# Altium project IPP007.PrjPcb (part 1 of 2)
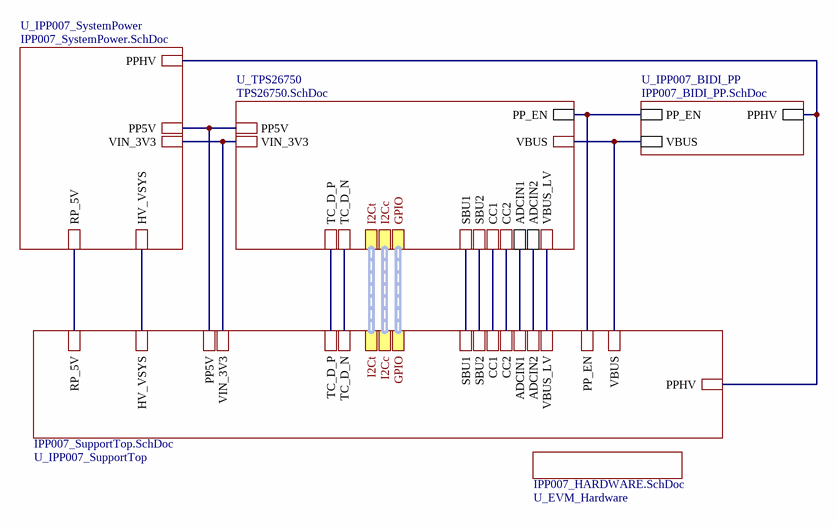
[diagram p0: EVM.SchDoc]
CopyrightYear: 2025; PCB_Layout: Chuck Branch; PCB_Rev: A3; PRJ_Customer: Public Release; PRJ_Engineer: Conner Gillette; PRJ_Number: IPP007; PRJ_Title: TPS26750 EVM; SCH_Rev: A3; TechSupport: http://www.ti.com/support; TID: 11450
12 sheets, 258 parts. Net scope: hierarchical (ports join the sheet entries above them; power ports are global).
Board file: IPP007_EVM.PcbDoc
Sheets:
  EVM.SchDoc
    U_EVM_Hardware = IPP007_HARDWARE.SchDoc
    U_TPS26750 = TPS26750.SchDoc
      U_MD = MOISTURE_DETECT.SchDoc
    U_IPP007_SystemPower = IPP007_SystemPower.SchDoc
      U_PP5V_SUPPLY = PP5V_SUPPLY.SchDoc
      U_IPP007_TC_POWER = IPP007_TC_POWER.SchDoc
    U_IPP007_SupportTop = IPP007_SupportTop.SchDoc
      U_IPP007_CONNECTORS = IPP007_CONNECTORS.SchDoc
      U_IPP007_RP_HOST = IPP007_RP_HOST.SchDoc
      U_IPP007_HUB = IPP007_HUB.SchDoc
    U_IPP007_BIDI_PP = IPP007_BIDI_PP.SchDoc

## Sheet EVM.SchDoc
size 431 x 279 mm; Date: Not shown in title block; ApprovedBy: Not shown in title block; CheckedBy: Not shown in title block; Author: Not shown in title block; CompanyName: Not shown in title block; Engineer: Not shown in title block; Organization: Not shown in title block; Address1: Not shown in title block; Address2: Not shown in title block; Address3: Not shown in title block; Address4: Not shown in title block; DocumentNumber: 1; Revision: Use project parameter SCH_Rev; SheetNumber: 1; SheetTotal: 14; PageSetup: Record=PageOptions¦CenterHorizontal=True¦CenterVertical=True¦PrintScale=0.97¦XCorrection=1.00¦YCorrection=1.00¦PrintKind=0¦BorderSize=5000000¦LeftOffset=0¦BottomOffset=0¦Orientation=2¦PaperLength=1000¦PaperWidth=1000¦Scale=100¦PaperSource=15¦PrintQuality=600¦MediaType=1¦DitherType=10¦PaperKind=Letter¦PrintScaleMode=1

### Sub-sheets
U_EVM_Hardware = IPP007_HARDWARE.SchDoc: no entries
U_IPP007_BIDI_PP = IPP007_BIDI_PP.SchDoc: PP_EN, VBUS, PPHV
U_IPP007_SupportTop = IPP007_SupportTop.SchDoc: CC1, CC2, PP_EN, ADCIN1, ADCIN2, HV_VSYS, PPHV, VBUS, VBUS_LV, PP5V, VIN_3V3, RP_5V, SBU1, SBU2, TC_D_P, TC_D_N, I2Ct (harness I2C), I2Cc (harness I2C), GPIO (harness GPIO)
U_IPP007_SystemPower = IPP007_SystemPower.SchDoc: HV_VSYS, PP5V, VIN_3V3, RP_5V, PPHV
U_TPS26750 = TPS26750.SchDoc: CC1, CC2, ADCIN2, ADCIN1, PP_EN, VBUS, VBUS_LV, PP5V, VIN_3V3, SBU1, SBU2, TC_D_P, TC_D_N, I2Ct (harness I2C), I2Cc (harness I2C), GPIO (harness GPIO)

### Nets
ADCIN1: sheet U_TPS26750/ADCIN1, sheet U_IPP007_SupportTop/ADCIN1
ADCIN2: sheet U_TPS26750/ADCIN2, sheet U_IPP007_SupportTop/ADCIN2
CC1: sheet U_TPS26750/CC1, sheet U_IPP007_SupportTop/CC1
CC2: sheet U_TPS26750/CC2, sheet U_IPP007_SupportTop/CC2
D3_N: sheet U_TPS26750/TC_D_N, sheet U_IPP007_SupportTop/TC_D_N
D3_P: sheet U_TPS26750/TC_D_P, sheet U_IPP007_SupportTop/TC_D_P
HV_VSYS: sheet U_IPP007_SystemPower/HV_VSYS, sheet U_IPP007_SupportTop/HV_VSYS
PP5V: sheet U_TPS26750/PP5V, sheet U_IPP007_SystemPower/PP5V, sheet U_IPP007_SupportTop/PP5V
PP_EN: sheet U_TPS26750/PP_EN, sheet U_IPP007_SupportTop/PP_EN, sheet U_IPP007_BIDI_PP/PP_EN
PPHV: sheet U_IPP007_SystemPower/PPHV, sheet U_IPP007_SupportTop/PPHV, sheet U_IPP007_BIDI_PP/PPHV
RP_5V: sheet U_IPP007_SystemPower/RP_5V, sheet U_IPP007_SupportTop/RP_5V
SBU1: sheet U_TPS26750/SBU1, sheet U_IPP007_SupportTop/SBU1
SBU2: sheet U_TPS26750/SBU2, sheet U_IPP007_SupportTop/SBU2
VBUS: sheet U_TPS26750/VBUS, sheet U_IPP007_SupportTop/VBUS, sheet U_IPP007_BIDI_PP/VBUS
VBUS_LV: sheet U_TPS26750/VBUS_LV, sheet U_IPP007_SupportTop/VBUS_LV
VIN_3V3: sheet U_TPS26750/VIN_3V3, sheet U_IPP007_SystemPower/VIN_3V3, sheet U_IPP007_SupportTop/VIN_3V3

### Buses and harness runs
harness sheet U_IPP007_SupportTop/GPIO = sheet U_TPS26750/GPIO
harness sheet U_IPP007_SupportTop/I2Cc = sheet U_TPS26750/I2Cc
harness sheet U_IPP007_SupportTop/I2Ct = sheet U_TPS26750/I2Ct

## Sheet IPP007_HARDWARE.SchDoc
size 431 x 279 mm; Date: Not shown in title block; ApprovedBy: Not shown in title block; CheckedBy: Not shown in title block; Author: Not shown in title block; CompanyName: Not shown in title block; Engineer: Not shown in title block; Organization: Not shown in title block; Address1: Not shown in title block; Address2: Not shown in title block; Address3: Not shown in title block; Address4: Not shown in title block; DocumentNumber: 14; Revision: Use project parameter SCH_Rev; SheetNumber: 14; SheetTotal: 14; PageSetup: Record=PageOptions¦CenterHorizontal=True¦CenterVertical=True¦PrintScale=0.97¦XCorrection=1.00¦YCorrection=1.00¦PrintKind=0¦BorderSize=5000000¦LeftOffset=0¦BottomOffset=0¦Orientation=2¦PaperLength=1000¦PaperWidth=1000¦Scale=100¦PaperSource=15¦PrintQuality=600¦MediaType=1¦DitherType=10¦PaperKind=Letter¦PrintScaleMode=1
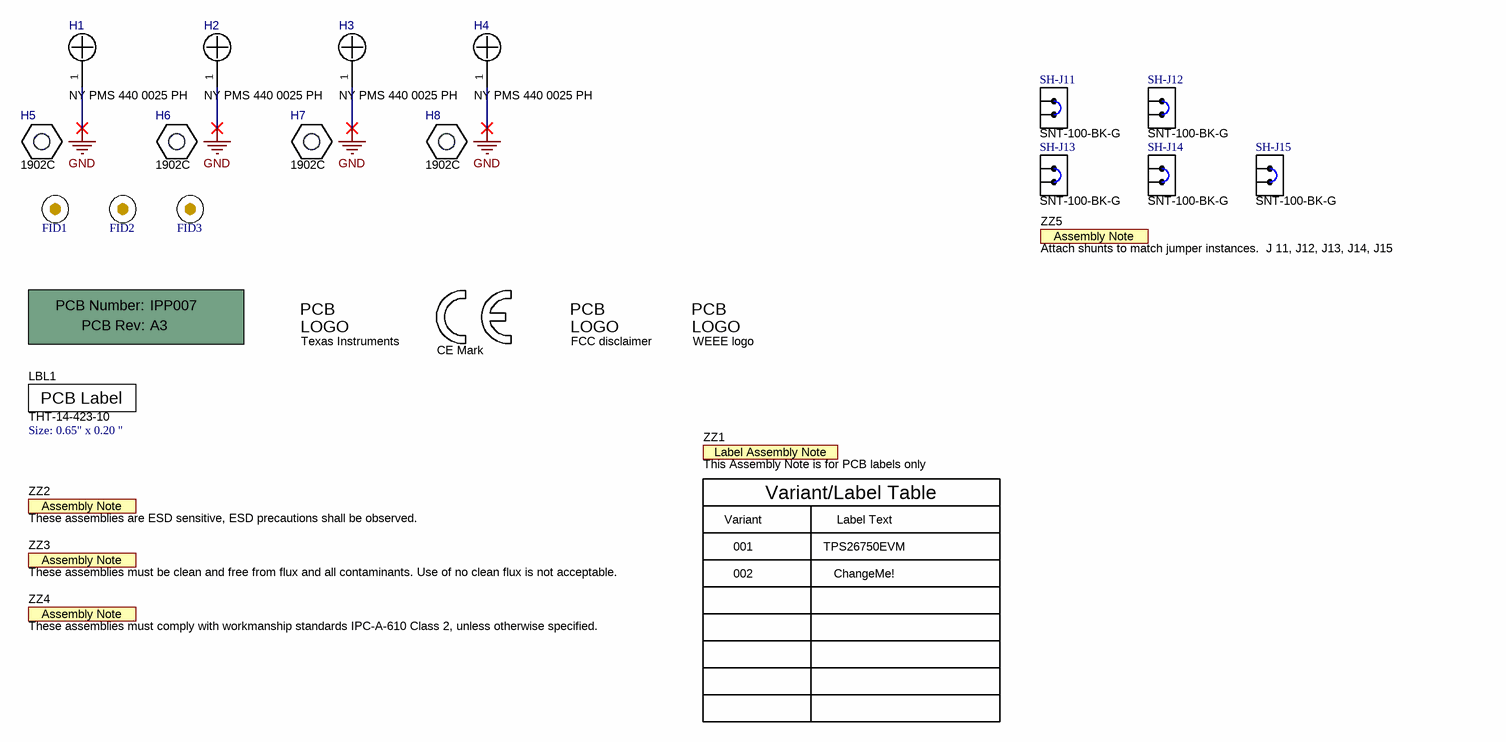
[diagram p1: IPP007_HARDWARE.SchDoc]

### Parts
!PCB1  Printed Circuit Board  (value not drawn)  (mechanical)
FID1  Fiducial  [Fiducial10-20]  (value not drawn)
FID2  Fiducial  [Fiducial10-20]  (value not drawn)
FID3  Fiducial  [Fiducial10-20]  (value not drawn)
H1  NY PMS 440 0025 PH  [NY PMS 440 0025 PH]
H2  NY PMS 440 0025 PH  [NY PMS 440 0025 PH]
H3  NY PMS 440 0025 PH  [NY PMS 440 0025 PH]
H4  NY PMS 440 0025 PH  [NY PMS 440 0025 PH]
H5  1902C  [Keystone_1902C]
H6  1902C  [Keystone_1902C]
H7  1902C  [Keystone_1902C]
H8  1902C  [Keystone_1902C]
LBL1  THT-14-423-10  Note: Size: 0.65" x 0.20 "  [Label_650x200]
Logo1  CE Mark  [CE_Mark_5mm]  (no BOM)
Logo2  Texas Instruments  [TI_Symbol_Overlay_Small]  (no BOM)
Logo3  FCC disclaimer  [FCC_disclaimer_stacked]  (no BOM)
Logo4  WEEE logo  [WEEE_Minimum]  (no BOM)
SH-J11  SNT-100-BK-G  [SNT-100-BK-G]
SH-J12  SNT-100-BK-G  [SNT-100-BK-G]
SH-J13  SNT-100-BK-G  [SNT-100-BK-G]
SH-J14  SNT-100-BK-G  [SNT-100-BK-G]
SH-J15  SNT-100-BK-G  [SNT-100-BK-G]
ZZ1  This Assembly Note is for PCB labels only  [AssemblyNoteLabel]  (no BOM)
ZZ2  These assemblies are ESD sensitive, ESD precautions shall be observed.  [AssemblyNote]  (no BOM)
ZZ3  These assemblies must be clean and free from flux and all contaminants. Use of no clean flux is not acceptable.  [AssemblyNote]  (no BOM)
ZZ4  These assemblies must comply with workmanship standards IPC-A-610 Class 2, unless otherwise specified.  [AssemblyNote]  (no BOM)
ZZ5  Attach shunts to match jumper instances.  J 11, J12, J13, J14, J15  [AssemblyNote]  (no BOM)

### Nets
GND: H1.1 H2.1 H3.1 H4.1

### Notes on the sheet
- Variant
- 001
- (near ZZ1) Variant/Label Table
- Label Text
- TPS26750EVM
- 002
- ChangeMe!

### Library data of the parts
!PCB1 = CMP-0003618-2: Manufacturer: Any; PartNumber: IPP007
FID1-FID3 = CMP-0077181-1: Fiducial mark.  There is nothing to buy or mount.
H1-H4 = CMP-0003617-1: Machine Screw, Round, #4-40 x 1/4, Nylon, Philips panhead; Manufacturer: B&F Fastener Supply; CompType: Hardware
H5-H8 = CMP-0003610-1: Standoff, Hex, 0.5"L #4-40 Nylon; Manufacturer: Keystone; CompType: Hardware
LBL1 = CMP-0003625-1: Thermal Transfer Printable Labels, 0.650" W x 0.200" H - 10,000 per roll; Manufacturer: Brady
Logo1 = CMP-0074844-1: SymbolCreator: a0412235
Logo2 = CMP-0074838-1: Texas Instrument Corporate Signature; SymbolCreator: a0412235; Lib Reference: TI_Logo
Logo3 = CMP-0074847-1: FCC_disclaimer
Logo4 = CMP-0074769-3: Manufacturer: Texas Instruments; CompType: IC; AEC Category: Q200
SH-J11-SH-J15 = CMP-0003623-3: Shunt, 100mil, Gold plated, Black; Manufacturer: Samtec; Alternate Manufacturer: 3M; Alternate PartNumber: 969102-0000-DA; Value: 1x2; Note: You can "mate" this to a header by matching the designator.  i.e. use SH-J3 for header J3
ZZ1 = CMP-0003616-3
ZZ2 = CMP-0077236-1
ZZ3 = CMP-0077237-1
ZZ4 = CMP-0077238-1
ZZ5 = CMP-0077238-1: These assemblies must comply with workmanship standards IPC-A-610 Class 2, unless otherwise specified.

## Sheet TPS26750.SchDoc
size 558 x 431 mm; Date: Not shown in title block; ApprovedBy: Not shown in title block; CheckedBy: Not shown in title block; Author: Not shown in title block; CompanyName: Not shown in title block; Engineer: Not shown in title block; Organization: Not shown in title block; Address1: Not shown in title block; Address2: Not shown in title block; Address3: Not shown in title block; Address4: Not shown in title block; DocumentNumber: 2; Revision: Use project parameter SCH_Rev; SheetNumber: 2; SheetTotal: 14; PageSetup: Record=PageOptions¦CenterHorizontal=True¦CenterVertical=True¦PrintScale=1.00¦XCorrection=1.00¦YCorrection=1.00¦PrintKind=0¦BorderSize=5000000¦LeftOffset=0¦BottomOffset=0¦Orientation=2¦PaperLength=1000¦PaperWidth=1000¦Scale=100¦PaperSource=15¦PrintQuality=600¦MediaType=1¦DitherType=10¦PaperKind=Letter¦PrintScaleMode=1
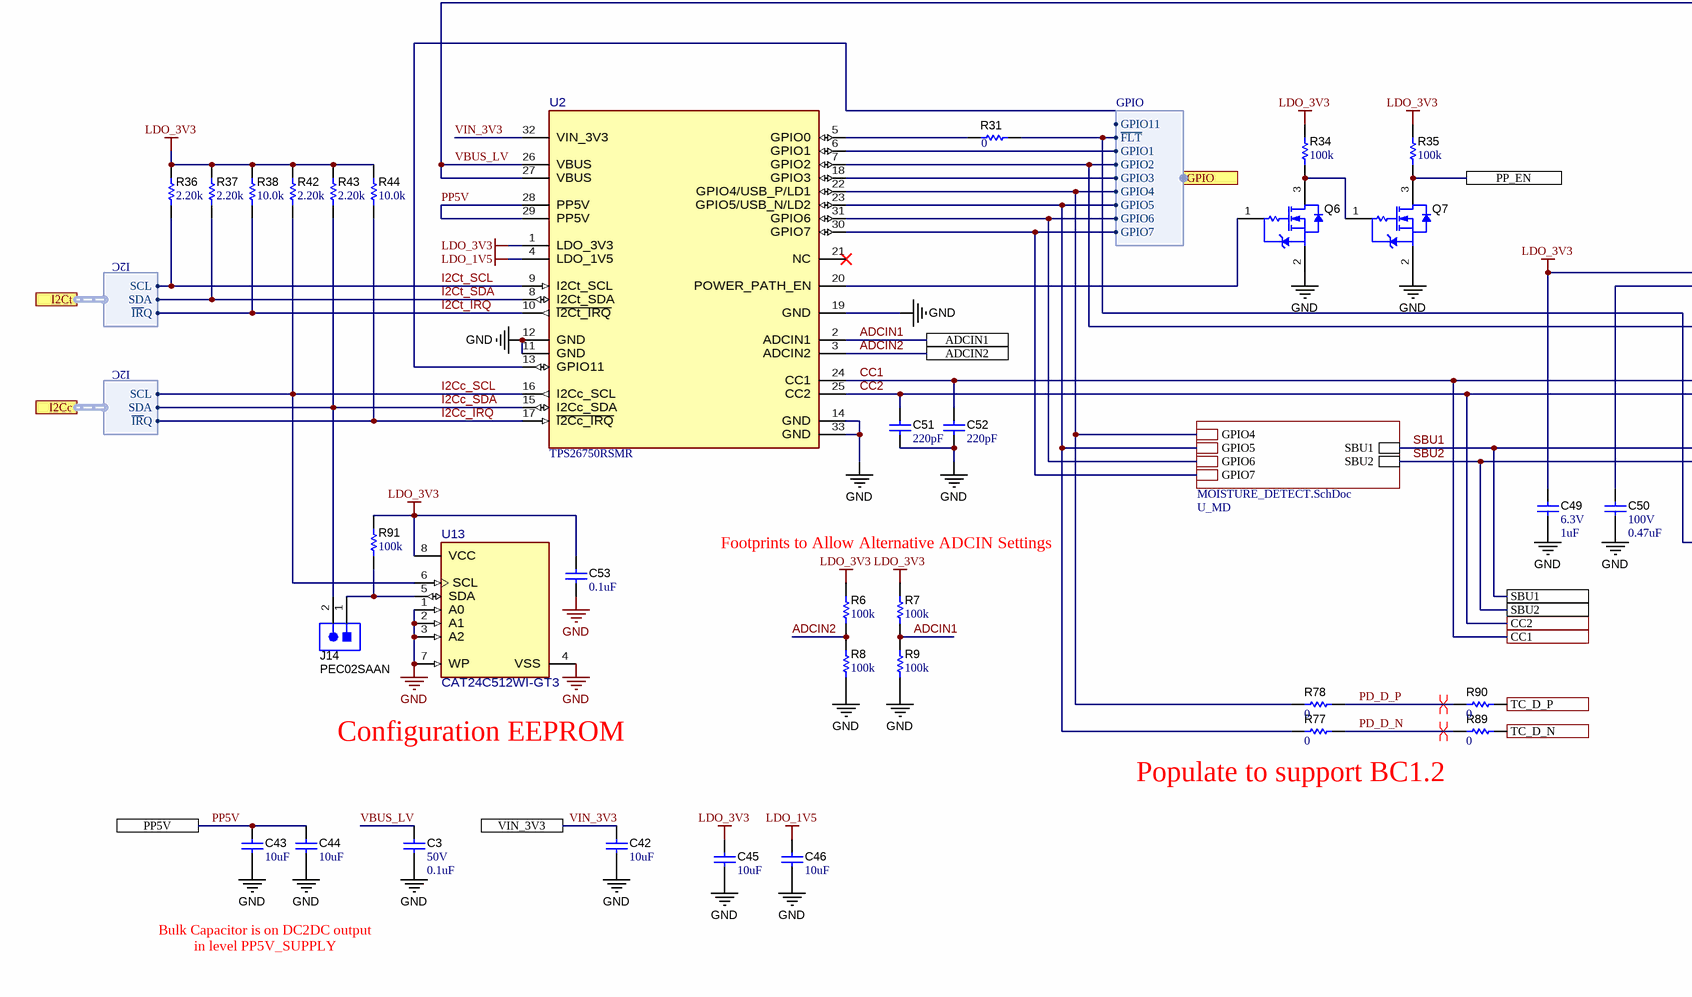
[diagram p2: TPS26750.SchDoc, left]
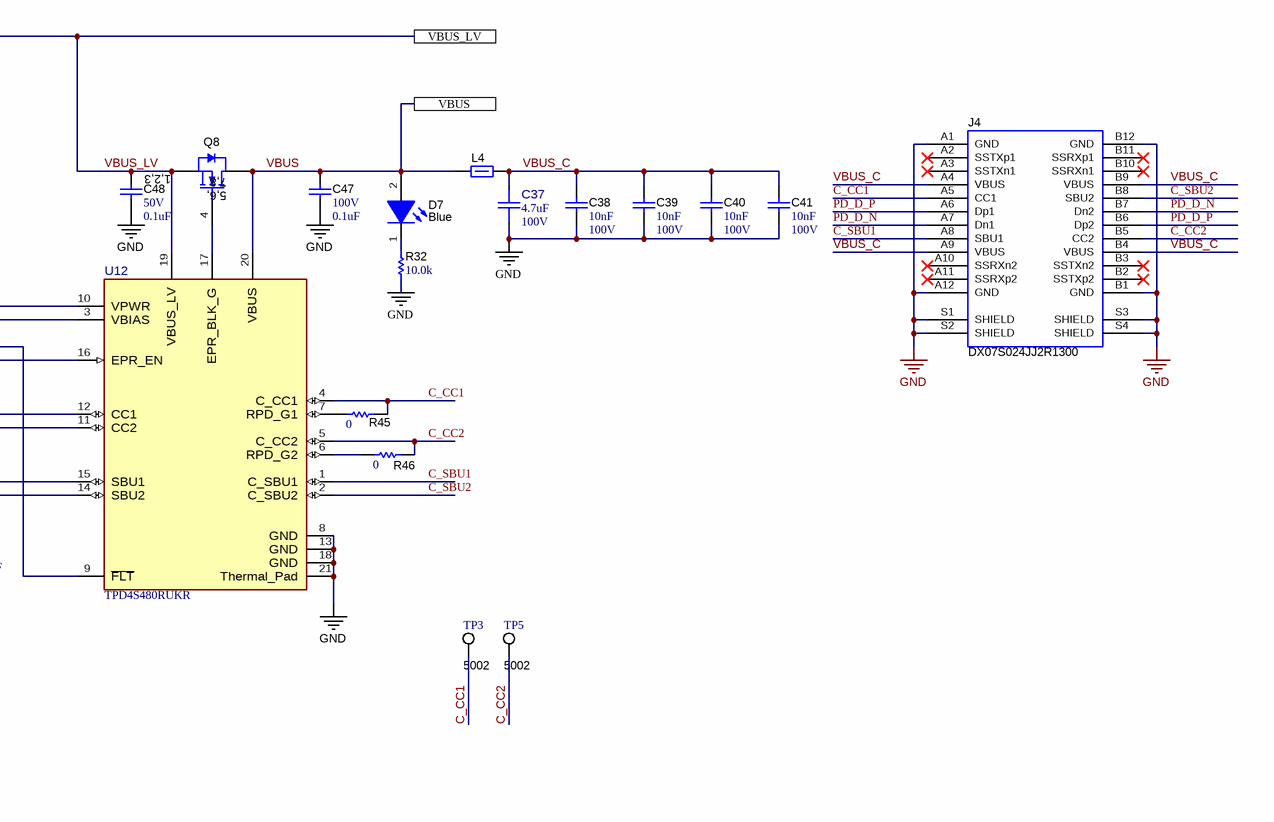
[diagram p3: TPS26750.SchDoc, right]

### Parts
C3  VDC_V: 50V  ValueDisplayed: 0.1uF  [0402L]  (hidden comment: C1005X5R1H104K050BB)
C37  ValueDisplayed: 4.7uF  VDC_V: 100V  [FP-C2012X5R2A475K125AC_0805-MFG]  (hidden comment: C2012X5R2A475K125AC)
C38  Cap_F: 10nF  VDC_V: 100V  [0603L]  (hidden comment: C0603X103K1RACTU)
C39  Cap_F: 10nF  VDC_V: 100V  [0603L]  (hidden comment: C0603X103K1RACTU)
C40  Cap_F: 10nF  VDC_V: 100V  [0603L]  (hidden comment: C0603X103K1RACTU)
C41  Cap_F: 10nF  VDC_V: 100V  [0603L]  (hidden comment: C0603X103K1RACTU)
C42  ValueDisplayed: 10uF  [0402_070]  (hidden comment: CL05A106MP5NUNC)
C43  ValueDisplayed: 10uF  [0603L]  (hidden comment: GRM188R61E106MA73D)
C44  ValueDisplayed: 10uF  [0603L]  (hidden comment: GRM188R61E106MA73D)
C45  ValueDisplayed: 10uF  [0402_070]  (hidden comment: CL05A106MP5NUNC)
C46  ValueDisplayed: 10uF  [0402_070]  (hidden comment: CL05A106MP5NUNC)
C47  VDC_V: 100V  ValueDisplayed: 0.1uF  [0402L]  (hidden comment: GRM155R62A104KE14D)
C48  VDC_V: 50V  ValueDisplayed: 0.1uF  [0402L]  (hidden comment: C1005X5R1H104K050BB)
C49  VDC_V: 6.3V  ValueDisplayed: 1uF  [0201_033]  (hidden comment: GRM033R60J105MEA2D)
C50  VDC_V: 100V  ValueDisplayed: 0.47uF  [1206_180]  (hidden comment: C3216X7R2A474K160AA)
C51  ValueDisplayed: 220pF  [0201_033L]  (hidden comment: CGA1A2X7R1H221K030BA)
C52  ValueDisplayed: 220pF  [0201_033L]  (hidden comment: CGA1A2X7R1H221K030BA)
C53  ValueDisplayed: 0.1uF  [0402L]  (hidden comment: CGA2B3X7R1H104K050BB)
D7  value Blue  [WL-SMCW_Blue]  (hidden comment: 150060BS75000)
J4  DX07S024JJ2R1300  [JAE_DX07S024JJ2R1300]
J14  PEC02SAAN  [CONN_PEC02SAAN]
L4  742792021  [0805L]  (value not drawn)
Q6  CSD17484F4T  [YJJ0003A]  (value not drawn)
Q7  CSD17484F4T  [YJJ0003A]  (value not drawn)
Q8  CSD17581Q3A  [DNH0008A]  (value not drawn)
R6  ValueDisplayed: 100k  [0603L]  (hidden comment: RC0603FR-07100KL)
R7  ValueDisplayed: 100k  [0603L]  (hidden comment: RC0603FR-07100KL)
R8  ValueDisplayed: 100k  [0603L]  (hidden comment: RC0603FR-07100KL)
R9  ValueDisplayed: 100k  [0603L]  (hidden comment: RC0603FR-07100KL)
R31  ValueDisplayed: 0  [0402]  (hidden comment: CRCW04020000Z0ED)
R32  ValueDisplayed: 10.0k  [0402L]  (hidden comment: CRCW040210K0FKED)
R34  ValueDisplayed: 100k  [0201L]  (hidden comment: RC0201FR-07100KL)
R35  ValueDisplayed: 100k  [0201L]  (hidden comment: RC0201FR-07100KL)
R36  ValueDisplayed: 2.20k  [0201L]  (hidden comment: CRCW02012K20FKED)
R37  ValueDisplayed: 2.20k  [0201L]  (hidden comment: CRCW02012K20FKED)
R38  ValueDisplayed: 10.0k  [0201L]  (hidden comment: CRCW020110K0FKED)
R42  ValueDisplayed: 2.20k  [0201L]  (hidden comment: CRCW02012K20FKED)
R43  ValueDisplayed: 2.20k  [0201L]  (hidden comment: CRCW02012K20FKED)
R44  ValueDisplayed: 10.0k  [0201L]  (hidden comment: CRCW020110K0FKED)
R45  ValueDisplayed: 0  [0201L]  (hidden comment: CRCW02010000Z0ED)
R46  ValueDisplayed: 0  [0201L]  (hidden comment: CRCW02010000Z0ED)
R77  ValueDisplayed: 0  [0201L]  (hidden comment: CRCW02010000Z0ED)
R78  ValueDisplayed: 0  [0201L]  (hidden comment: CRCW02010000Z0ED)
R89  ValueDisplayed: 0  [0201L]  (hidden comment: CRCW02010000Z0ED)
R90  ValueDisplayed: 0  [0201L]  (hidden comment: CRCW02010000Z0ED)
R91  ValueDisplayed: 100k  [0201L]  (hidden comment: RC0201FS-7D100KL)
TP3  5002  [Keystone5002]
TP5  5002  [Keystone5002]
U2  TPS26750RSMR  [RSM0032B-MFG]
U12  TPD4S480RUKR  [RUK0020B-MFG]
U13  CAT24C512WI-GT3  [FP-CAT24C512WI-GT3_SOIC8-IPC_C]

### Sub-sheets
U_MD = MOISTURE_DETECT.SchDoc: SBU1, SBU2, GPIO6, GPIO7, GPIO4, GPIO5

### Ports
ADCIN1, ADCIN2, CC1, CC2, GPIO (harness GPIO), I2Cc (harness I2C), I2Ct (harness I2C), PP5V, PP_EN, SBU1, SBU2, TC_D_N, TC_D_P, VBUS, VBUS_LV, VIN_3V3

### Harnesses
I2C: ~{IR}Q, SDA, SCL
GPIO: ~{FLT}, GPIO1, GPIO2, GPIO3, GPIO4, GPIO5, GPIO6, GPIO7, GPIO11

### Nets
GND: C3.2 C37.1 C38.2 C39.2 C40.2 C41.2 C42.2 C43.2 C44.2 C45.1 C46.1 C47.2 C48.2 C49.2 C50.2 C51.2 C52.2 C53.2 J4.A1(GND) J4.A12(GND) J4.B1(GND) J4.B12(GND) J4.S1(SHIELD) J4.S2(SHIELD) J4.S3(SHIELD) J4.S4(SHIELD) Q6.2(S) Q7.2(S) R8.1 R9.1 R32.1 U2.11(GND) U2.12(GND) U2.14(GND) U2.19(GND) U2.33(GND) U12.8(GND) U12.13(GND) U12.18(GND) U12.21(Thermal_Pad) U13.1(A0) U13.2(A1) U13.3(A2) U13.4(VSS) U13.7(WP)
LDO_1V5: C46.2 U2.4(LDO_1V5)
LDO_3V3: C45.2 C49.1 C53.1 R6.2 R7.2 R34.2 R35.2 R36.1 R37.1 R38.1 R42.1 R43.1 R44.1 R91.2 U2.1(LDO_3V3) U12.10(VPWR) U13.8(VCC)
ADCIN1: R7.1 R9.2 U2.2(ADCIN1) ; port ADCIN1
ADCIN2: R6.1 R8.2 U2.3(ADCIN2) ; port ADCIN2
C_CC1: J4.A5(CC1) R45.2 TP3.1 U12.4(C_CC1)
C_CC2: J4.B5(CC2) R46.2 TP5.1 U12.5(C_CC2)
C_SBU1: J4.A8(SBU1) U12.1(C_SBU1)
C_SBU2: J4.B8(SBU2) U12.2(C_SBU2)
CC1: C52.1 U2.24(CC1) U12.12(CC1) ; port CC1
CC2: C51.1 U2.25(CC2) U12.11(CC2) ; port CC2
D3_N: R89.2 ; port TC_D_N
D3_P: R90.2 ; port TC_D_P
GPIO4: R78.1 U2.22(GPIO4/USB_P/LD1) ; sheet U_MD/GPIO4, port GPIO.GPIO4
GPIO5: R77.1 U2.23(GPIO5/USB_N/LD2) ; sheet U_MD/GPIO5, port GPIO.GPIO5
GPIO6: U2.31(GPIO6) ; sheet U_MD/GPIO6, port GPIO.GPIO6
GPIO7: U2.30(GPIO7) ; sheet U_MD/GPIO7, port GPIO.GPIO7
I2Cc_SCL: R42.2 U2.16(I2Cc_SCL) U13.6(SCL) ; port I2Cc.SCL
I2Cc_SDA: J14.2 R43.2 U2.15(I2Cc_SDA) ; port I2Cc.SDA
I2Ct_SCL: R36.2 U2.9(I2Ct_SCL) ; port I2Ct.SCL
I2Ct_SDA: R37.2 U2.8(I2Ct_SDA) ; port I2Ct.SDA
~{I2Cc_IRQ}: R44.2 U2.17(~{I2Cc_IRQ}) ; port I2Cc.~{IR}Q
~{I2Ct_IRQ}: R38.2 U2.10(~{I2Ct_IRQ}) ; port I2Ct.~{IR}Q
PD_D_N: J4.A7(Dn1) J4.B7(Dn2) R77.2 R89.1
PD_D_P: J4.A6(Dp1) J4.B6(Dp2) R78.2 R90.1
PP5V: C43.1 C44.1 U2.28(PP5V) U2.29(PP5V) ; port PP5V
PP_EN: Q7.3(D) R35.1 ; port PP_EN
SBU1: U12.15(SBU1) ; port SBU1, sheet U_MD/SBU1
SBU2: U12.14(SBU2) ; port SBU2, sheet U_MD/SBU2
VBUS: C47.1 D7.2(A) L4.1 Q8.5(D) Q8.6(D) Q8.7(D) Q8.8(D) Q8.9(D) U12.20(VBUS) ; port VBUS
VBUS_C: C37.2 C38.1 C39.1 C40.1 C41.1 J4.A4(VBUS) J4.A9(VBUS) J4.B4(VBUS) J4.B9(VBUS) L4.2
VBUS_LV: C3.1 C48.1 Q8.1(S) Q8.2(S) Q8.3(S) U2.26(VBUS) U2.27(VBUS) U12.19(VBUS_LV) ; port VBUS_LV
VIN_3V3: C42.1 U2.32(VIN_3V3) ; port VIN_3V3
NetC50_1: C50.1 U12.3(VBIAS)
NetD7_1: D7.1(K) R32.2
NetJ2_5: U2.18(GPIO3) ; port GPIO.GPIO3
NetJ2_6: U2.13(GPIO11) ; port GPIO.GPIO11
NetJ2_9: U2.7(GPIO2) U12.16(EPR_EN) ; port GPIO.GPIO2
NetJ2_11: U2.6(GPIO1) ; port GPIO.GPIO1
NetJ2_13: R31.2 U12.9(~{FLT}) ; port GPIO.~{FLT}
NetJ14_1: J14.1 R91.1 U13.5(SDA)
NetQ6_1: Q6.1(G) U2.20(POWER_PATH_EN)
NetQ6_3: Q6.3(D) Q7.1(G) R34.1
NetQ8_4: Q8.4(G) U12.17(EPR_BLK_G)
NetR31_1: R31.1 U2.5(GPIO0)
NetR45_1: R45.1 U12.7(RPD_G1)
NetR46_1: R46.1 U12.6(RPD_G2)

Not connected (* = marked no-connect by the designer): J4 A2(SSTXp1)* A3(SSTXn1)* A10(SSRXn2)* A11(SSRXp2)* B2(SSTXp2)* B3(SSTXn2)* B10(SSRXn1)* B11(SSRXp1)*; U2 21(NC)*

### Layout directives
differential pair: PD_D_N, PD_D_P

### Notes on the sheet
- Footprints to Allow Alternative ADCIN Settings
- (near U13) Configuration EEPROM
- Populate to support BC1.2
- Bulk Capacitor is on DC2DC output in level PP5V_SUPPLY

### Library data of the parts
C3 C48 = CMP-0006279-2: CAP, CERM, 0.1 uF, 50 V, +/- 10%, X5R, 0402; Manufacturer: TDK; TaMin_C: -55°C; ESR_ohm: 39.064m; Polarized: N; SizeAreaWB_mm2: 3; Value1: 0.039064 ohm; U/M: EA; Value: 0.1uF; TaMax_C: 85°C; SizeZ_mm: 0.6; SizeX_mm: 1; SizeY_mm: 0.5; Cap_Case: 0402; Cap_F: 100nF; IRMS_A: 814.669mA; AEC Category: Q200
C37 = CMP-0098058-1: 4.7 µF ±10% 100V Ceramic Capacitor X5R 0805 (2012 Metric); Manufacturer: TDK; AEC Qualified: No; SizeZ_mm: 1.5mm; Value: 4.7µF; TempCo: 15%
C38-C41 = CMP-0006977-4: CAP, CERM, 0.01 uF, 100 V, +/- 10%, X7R, 0603; Manufacturer: Kemet; TaMin_C: -55°C; Polarized: N; SizeAreaWB_mm2: 4.68; Value1: Unknown; U/M: EA; Value: 0.01uF; TaMax_C: 125°C; SizeZ_mm: 1; SizeX_mm: 1.6; SizeY_mm: 0.8; Cap_Case: 0603; SizeArea_mm2: 1.28; AEC Category: Q200
C42 C45 C46 = CMP-0006339-4: CAP, CERM, 10 uF, 10 V, +/- 20%, X5R, 0402; Manufacturer: Samsung Electro-Mechanics; TaMin_C: -55°C; Polarized: N; SizeAreaWB_mm2: 3; Value1: Unknown; U/M: EA; Value: 10uF; TaMax_C: 85°C; SizeZ_mm: 0.6; SizeX_mm: 1; SizeY_mm: 0.5; Cap_Case: 0402; Value2: 10V; Cap_F: 10µF; AEC Category: Q200
C43 C44 = CMP-0007344-5: CAP, CERM, 10 uF, 25 V, +/- 20%, X5R, 0603; Manufacturer: MuRata; TaMin_C: -55°C; Polarized: N; SizeAreaWB_mm2: 4.68; Value1: Unknown; U/M: EA; Value: 10uF; TaMax_C: 85°C; SizeZ_mm: 1; SizeX_mm: 1.6; SizeY_mm: 0.8; Cap_Case: 0603; Value2: 25V; SizeArea_mm2: 1.28; Cap_F: 10µF; AEC Category: Q200
C47 = CMP-0006618-2: CAP, CERM, 0.1 uF, 100 V, +/- 10%, X5R, 0402; Manufacturer: MuRata; TaMin_C: -55°C; Polarized: N; SizeAreaWB_mm2: 3; Value1: Unknown; U/M: EA; Value: 0.1uF; TaMax_C: 85°C; SizeZ_mm: 0.6; SizeX_mm: 1; SizeY_mm: 0.5; Cap_Case: 0402; Cap_F: 100nF; AEC Category: Q200
C49 = CMP-0009692-3: CAP, CERM, 1 uF, 6.3 V, +/- 20%, X5R, 0201; Manufacturer: MuRata; Value: 1uF; SizeZ_mm: 0.33; AEC Qualified: N; Cap_F: 1µF; TaMin_C: -55°C; SizeAreaWB_mm2: 2.08; Value1: Unknown; U/M: EA; TaMax_C: 85°C; SizeX_mm: 0.6; SizeY_mm: 0.3; Cap_Case: 0201; SizeArea_mm2: 0.18; AEC Category: Q200
C50 = CMP-0008716-2: CAP, CERM, 0.47 uF, 100 V, +/- 10%, X7R, 1206; Manufacturer: TDK; TaMin_C: -55°C; ESR_ohm: 7.558m; Polarized: N; SizeAreaWB_mm2: 10.92; Value1: 0.007558 ohm; U/M: EA; Value: 0.47uF; TaMax_C: 125°C; SizeZ_mm: 1.8; SizeX_mm: 3.2; SizeY_mm: 1.6; SizeArea_mm2: 5.12; Cap_F: 470nF; IRMS_A: 2.6472A; AEC Category: Q200
C51 C52 = CMP-0009652-3: CAP, CERM, 220 pF, 50 V, +/- 10%, X7R, AEC-Q200 Grade 1, 0201; Manufacturer: TDK; TaMin_C: -55°C; ESR_ohm: 11.6275; Polarized: N; SizeAreaWB_mm2: 2.08; Value1: 11.6275 ohm; U/M: EA; Value: 220pF; TaMax_C: 125°C; SizeZ_mm: 0.33; SizeX_mm: 0.6; SizeY_mm: 0.3; Cap_Case: 0201_033; Value2: 50V; SizeArea_mm2: 0.18; AEC Qualified: Y; IRMS_A: 200.785mA; AEC Grade: 1; AEC Category: Q200
C53 = CMP-0006325-2: CAP, CERM, 0.1 uF, 50 V, +/- 10%, X7R, AEC-Q200 Grade 1, 0402; Manufacturer: TDK; TaMin_C: -55°C; ESR_ohm: 39.064m; Polarized: N; SizeAreaWB_mm2: 3; Value1: 0.039064 ohm; U/M: EA; Value: 0.1uF; TaMax_C: 125°C; SizeZ_mm: 0.6; SizeX_mm: 1; SizeY_mm: 0.5; Cap_Case: 0402; Value2: 50V; AEC Qualified: Y; Cap_F: 100nF; IRMS_A: 814.669mA; AEC Category: Q200
D7 = CMP-0002946-3: LED, Blue, SMD; Manufacturer: Wurth Elektronik; Io_A: 30mA; Power_TotalModule: 105mW; Vr_V: 5V; Tjmax_C: 85°C; Value1: 0.105W; Angle: 140; Vf_V: 3.2V; Type: InGaN
J4 = CMP-0085712-2: Receptacle, USB 3.1 Type C, R/A, Gold, SMT; Manufacturer: JAE Electronics; Current_A: 1.25A; Gender: Female; Voltage_V: 20V; Pitch_mm: 0.5; Row_Count: 2
J14 = CMP-0002337-1: Header, 100mil, 2x1, Tin, TH; Manufacturer: Sullins Connector Solutions; CNHeader: TRUE; Current_A: 3A; Green_Lifecycle: Not Set; Shrouded: N; Gender: Male; Green_REACh: Incomplete; Voltage_V: 1.8kV; Row_Count: 1; Pitch_mm: 2.54; CT: FALSE; Cert_UL: Y
L4 = CMP-0003072-1: Ferrite Bead, 22 ohm @ 100 MHz, 6 A, 0805; Manufacturer: Wurth Elektronik; Ztyp@1GHz_Ohm: 40.219; ZTyp@100MHz_Ohm: 22; SizeAreaWB_mm2: 6.75; DCR_ohm: 8m; Value1: 0.008 ohm; Value: 22 ohm; Imax_A: 6A; SizeZ_mm: 1.45; SizeX_mm: 2; SizeY_mm: 1.25; SizeArea_mm2: 2.5
Q6 Q7 = CMP-0000571-1: MOSFET, N-CH, 30 V, 3 A, YJJ0003A (PICOSTAR-3); Alternate Manufacturer: None; Manufacturer: Texas Instruments; SizeZ_mm: 0.22; ChType: N; Value2: 0.92 nC; Value1: 0.12; VdsMax_V: 30V; SizeX_mm: 1; SizeY_mm: 0.6; Vgs_V: 12V; Value: 30V; Rdson45_ohm: 0.128; AEC Category: Q101; IdsMax_A: 3A; SizeAreaWB_mm2: 3.2; U/M: EA; QgTyp_nC: 0.92
Q8 = CMP-0079500-2: MOSFET, N-CH, 30 V, 60 A, DNH0008A (VSONP-8); Manufacturer: Texas Instruments; Alternate Manufacturer: None; ChType: N; QgTyp_nC: 20; SizeAreaWB_mm2: 18.49; SizeArea_mm2: 10.89; IdsMax_A: 60A; VdsMax_V: 30V; Rdson45_ohm: 4.7m; Vgs_V: 20V; AEC Category: Q101; Value: 30V; SizeZ_mm: 0.9; SizeY_mm: 3.3; Value2: 20 nC; Value1: 0.0047 ohm; ChMode: Enhancement
R6-R9 = CMP-0022735-5: RES, 100 k, 1%, 0.1 W, 0603; Manufacturer: Yageo; Power_W: 100mW; TempCo: 100 ppm/C; Value: 100k; EIA_Code: E96; SizeX_mm: 1.6; SizeY_mm: 0.8; SizeZ_mm: 1; Value2: 0.1W; SizeArea_mm2: 1.28; AEC Qualified: N; VDC_V: 75V; AEC Category: Q200; SizeAreaWB_mm2: 4.68
R31 = CMP-0026822-1: RES, 0, 5%, 0.063 W, 0402; Manufacturer: Vishay-Dale; Power_W: 63mW; TempCo: 200 ppm/C; Value_Code: 0000; U/M: EA; Value: 0; EIA_Code: E24; SizeX_mm: 1; SizeY_mm: 0.5; SizeZ_mm: 0.6; Value2: 0.063W; VDC_V: 50V; AEC Category: Q200
R32 = CMP-0025958-3: RES, 10.0 k, 1%, 0.063 W, AEC-Q200 Grade 0, 0402; Manufacturer: Vishay-Dale; Power_W: 63mW; TempCo: 100 ppm/C; Value_Code: 10k0; Value: 10.0k; EIA_Code: E96; Res_ohm: 10k; SizeX_mm: 1; SizeY_mm: 0.5; SizeZ_mm: 0.6; Value2: 0.063W; AEC Qualified: Y; VDC_V: 50V; AEC Category: Q200; AEC Grade: 0
R34 R35 = CMP-0027293-2: RES, 100 k, 1%, 0.05 W, 0201; Manufacturer: Yageo America; Power_W: 50mW; TempCo: 200 ppm/C; U/M: EA; Value: 100k; EIA_Code: E96; SizeX_mm: 0.6; SizeY_mm: 0.3; SizeZ_mm: 0.26; Value2: 0.05W; SizeArea_mm2: 0.18; AEC Qualified: N; VDC_V: 25V; AEC Category: Q200
R36 R37 R42 R43 = CMP-0027272-3: RES, 2.20 k, 1%, 0.05 W, 0201; Manufacturer: Vishay-Dale; Power_W: 50mW; TempCo: 100 ppm/C; Value_Code: 2k20; Value: 2.20k; Res_ohm: 2.2k; SizeX_mm: 0.6; SizeY_mm: 0.3; SizeZ_mm: 0.26; Value2: 0.05W; SizeArea_mm2: 0.18; AEC Qualified: N; VDC_V: 30V; AEC Category: Q200
R38 R44 = CMP-0027262-3: RES, 10.0 k, 1%, 0.05 W, 0201; Manufacturer: Vishay-Dale; Power_W: 50mW; TempCo: 100 ppm/C; Value_Code: 10k0; Value: 10.0k; EIA_Code: E96; Res_ohm: 10k; SizeX_mm: 0.6; SizeY_mm: 0.3; SizeZ_mm: 0.26; Value2: 0.05W; SizeArea_mm2: 0.18; AEC Qualified: N; VDC_V: 30V; AEC Category: Q200
R45 R46 R77 R78 R89 R90 = CMP-0027008-4: RES, 0, 5%, 0.05 W, 0201; Manufacturer: Vishay-Dale; Power_W: 50mW; TempCo: ppm/C; Value_Code: 0000; Value: 0; EIA_Code: E24; SizeX_mm: 0.6; SizeY_mm: 0.3; SizeZ_mm: 0.26; Value2: 0.05W; SizeArea_mm2: 0.18; AEC Qualified: N; AEC Category: Q200
R91 = CMP-0028069-1: RES, 100 k, 1%, 0.05 W, 0201; Manufacturer: Yageo America; Power_W: 50mW; TempCo: 200 ppm/C; U/M: EA; Value: 100k; EIA_Code: E96; SizeX_mm: 0.6; SizeY_mm: 0.3; SizeZ_mm: 0.26; Value2: 0.05W; SizeArea_mm2: 0.18; AEC Qualified: N; VDC_V: 25V; AEC Category: Q200
TP3 TP5 = CMP-0055139-2: Test Point, Miniature, White, TH; Manufacturer: Keystone Electronics; ContactFinish: Silver; Green_REACh: Passed; CT: TRUE; Green_Lifecycle: Active; CNHeader: FALSE
U2 = CMP-0121143-2: USB Type-C® and USB PD Controller with Integrated Power Switches Optimized for Power Applications; Manufacturer: Texas Instruments; SizeZ_mm: 1mm; AEC Qualified: No; Interface: I2C,USB; Max Supply Voltage: 22V; Min Supply Voltage: 3V; Nominal Supply Current: 1-3mA; Number Of Ports: 1; Standoff Height: 0mm; TaMax_C: +85°C; TaMin_C: -40°C; TJmax_C: +125°C; Usb Standard: USB 3.1; AEC Category: Q200; CompType: IC
U12 = CMP-0034161-1: USB Type-C® 48V EPR Port Protector: Short-to-VBUS Overvoltage and IEC ESD Protection; Manufacturer: Texas Instruments; SizeZ_mm: 0.8mm; AEC Qualified: No; Direction: Bidirectional; Number Of Channels: 4; Operating Supply Voltage: 3.3V; Standoff Height: 0mm; TJmax_C: +125°C
U13 = CMP-0091847-1: EEPROM Memory IC 512Kb (64K x 8) I²C 1MHz 900ns 8-SOIC; Manufacturer: ON Semi; Standoff Height: 0.1mm; AEC Qualified: No; Max Supply Voltage: 5.5V; Interface: I2C; SizeZ_mm: 1.75mm; Memory Size: 512Kbits; Min Supply Voltage: 1.8V

## Sheet MOISTURE_DETECT.SchDoc
size 431 x 279 mm; Date: Not shown in title block; ApprovedBy: Not shown in title block; CheckedBy: Not shown in title block; Author: Not shown in title block; CompanyName: Not shown in title block; Engineer: Not shown in title block; Organization: Not shown in title block; Address1: Not shown in title block; Address2: Not shown in title block; Address3: Not shown in title block; Address4: Not shown in title block; DocumentNumber: 3; Revision: Use project parameter SCH_Rev; SheetNumber: 3; SheetTotal: 14; PageSetup: Record=PageOptions¦CenterHorizontal=True¦CenterVertical=True¦PrintScale=0.97¦XCorrection=1.00¦YCorrection=1.00¦PrintKind=0¦BorderSize=5000000¦LeftOffset=0¦BottomOffset=0¦Orientation=2¦PaperLength=1000¦PaperWidth=1000¦Scale=100¦PaperSource=15¦PrintQuality=600¦MediaType=1¦DitherType=10¦PaperKind=Letter¦PrintScaleMode=1
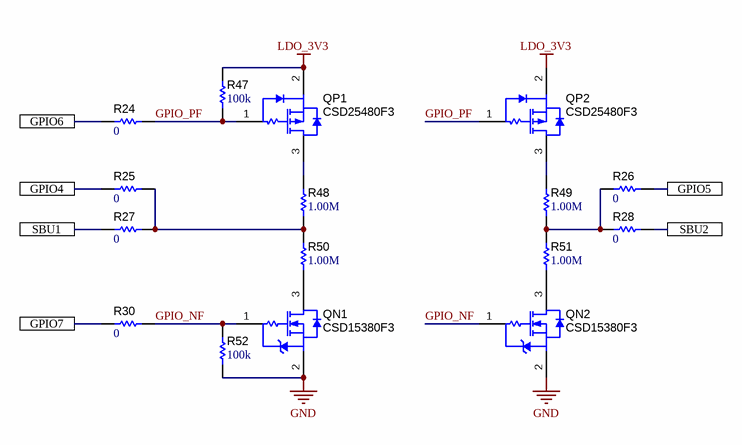
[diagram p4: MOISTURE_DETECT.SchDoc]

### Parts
QN1  CSD15380F3  [YJM0003A]
QN2  CSD15380F3  [YJM0003A]
QP1  CSD25480F3  [YJM0003A]
QP2  CSD25480F3  [YJM0003A]
R24  ValueDisplayed: 0  [0201L]  (hidden comment: CRCW02010000Z0ED)
R25  ValueDisplayed: 0  [0201L]  (hidden comment: CRCW02010000Z0ED)
R26  ValueDisplayed: 0  [0201L]  (hidden comment: CRCW02010000Z0ED)
R27  ValueDisplayed: 0  [0201L]  (hidden comment: CRCW02010000Z0ED)
R28  ValueDisplayed: 0  [0201L]  (hidden comment: CRCW02010000Z0ED)
R30  ValueDisplayed: 0  [0201L]  (hidden comment: CRCW02010000Z0ED)
R47  ValueDisplayed: 100k  [0402L]  (hidden comment: RC1005F104CS)
R48  ValueDisplayed: 1.00M  [0402L]  (hidden comment: ERJ-2RKF1004X)
R49  ValueDisplayed: 1.00M  [0402L]  (hidden comment: ERJ-2RKF1004X)
R50  ValueDisplayed: 1.00M  [0402L]  (hidden comment: ERJ-2RKF1004X)
R51  ValueDisplayed: 1.00M  [0402L]  (hidden comment: ERJ-2RKF1004X)
R52  ValueDisplayed: 100k  [0402L]  (hidden comment: RC1005F104CS)

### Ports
GPIO4, GPIO5, GPIO6, GPIO7, SBU1, SBU2

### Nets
GND: QN1.2(S) QN2.2(S) R52.1
LDO_3V3: QP1.2(S) QP2.2(S) R47.2
GPIO4: R25.1 ; port GPIO4
GPIO5: R26.2 ; port GPIO5
GPIO6: R24.1 ; port GPIO6
GPIO7: R30.1 ; port GPIO7
GPIO_NF: QN1.1(G) QN2.1(G) R30.2 R52.2
GPIO_PF: QP1.1(G) QP2.1(G) R24.2 R47.1
SBU1: R27.1 ; port SBU1
SBU2: R28.2 ; port SBU2
NetQN1_3: QN1.3(D) R50.1
NetQN2_3: QN2.3(D) R51.1
NetQP1_3: QP1.3(D) R48.2
NetQP2_3: QP2.3(D) R49.2
NetR25_2: R25.2 R27.2 R48.1 R50.2
NetR26_1: R26.1 R28.1 R49.1 R51.2

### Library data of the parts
QN1 QN2 = CMP-0000206-2: MOSFET, N-CH, 20 V, 0.5 A, YJM0003A (PICOSTAR-3); Alternate Manufacturer: None; Manufacturer: Texas Instruments; SizeZ_mm: 0.35; ChType: N; Value2: 0.216 nC; Value1: 1.4; VdsMax_V: 20V; SizeX_mm: 0.69; SizeY_mm: 0.6; Vgs_V: 10V; Value: 20V; Rdson45_ohm: 1.46; SizeArea_mm2: 0.414; AEC Category: Q101; IdsMax_A: 500mA; SizeAreaWB_mm2: 2.704; U/M: EA; QgTyp_nC: 0.216
QP1 QP2 = CMP-0000027-4: MOSFET, P-CH, -20 V, -1.7 A, YJM0003A (PICOSTAR-3); Alternate Manufacturer: None; Manufacturer: Texas Instruments; AEC Category: Q101; QgTyp_nC: 0.7; Vgs_V: -12V; Value2: 0.7 nC; Rdson45_ohm: 0.159; SizeY_mm: 0.6; SizeZ_mm: 0.35; SizeArea_mm2: 0.414; ChType: P; AEC Qualified: N; Value1: 0.15; ChMode: Enhancement; VdsMax_V: -20V; SizeX_mm: 0.69; Value: -20V; SizeAreaWB_mm2: 2.704; IdsMax_A: -1.7A
R24-R28 R30 = CMP-0027008-4: as R45 on sheet TPS26750
R47 R52 = CMP-0026745-1: RES, 100 k, 1%, 0.063 W, 0402; Manufacturer: Samsung Electro-Mechanics; Power_W: 63mW; TempCo: 100 ppm/C; U/M: EA; Value: 100k; EIA_Code: E96; SizeX_mm: 1; SizeY_mm: 0.5; SizeZ_mm: 0.6; Value2: 0.063W; AEC Qualified: N; VDC_V: 80V; AEC Category: Q200
R48-R51 = CMP-0026660-1: RES, 1.00 M, 1%, 0.1 W, 0402; Manufacturer: Panasonic; Power_W: 100mW; TempCo: 100 ppm/C; Value_Code: 1M00; U/M: EA; Value: 1.00Meg; EIA_Code: E96; Res_ohm: 1M; SizeX_mm: 1; SizeY_mm: 0.5; SizeZ_mm: 0.6; Value2: 0.1W; VDC_V: 50V; AEC Category: Q200

## Sheet IPP007_SystemPower.SchDoc
size 431 x 279 mm; Date: Not shown in title block; ApprovedBy: Not shown in title block; CheckedBy: Not shown in title block; Author: Not shown in title block; CompanyName: Not shown in title block; Engineer: Not shown in title block; Organization: Not shown in title block; Address1: Not shown in title block; Address2: Not shown in title block; Address3: Not shown in title block; Address4: Not shown in title block; DocumentNumber: 7; Revision: Use project parameter SCH_Rev; SheetNumber: 7; SheetTotal: 14; PageSetup: Record=PageOptions¦CenterHorizontal=True¦CenterVertical=True¦PrintScale=1.00¦XCorrection=1.00¦YCorrection=1.00¦PrintKind=0¦BorderSize=5000000¦LeftOffset=0¦BottomOffset=0¦Orientation=2¦PaperLength=1000¦PaperWidth=1000¦Scale=100¦PaperSource=15¦PrintQuality=600¦MediaType=1¦DitherType=10¦PaperKind=Letter¦PrintScaleMode=1
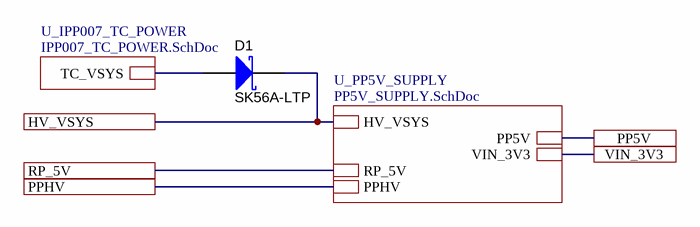
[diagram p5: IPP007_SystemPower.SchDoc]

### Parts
D1  SK56A-LTP  [SMA]

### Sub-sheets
U_IPP007_TC_POWER = IPP007_TC_POWER.SchDoc: TC_VSYS
U_PP5V_SUPPLY = PP5V_SUPPLY.SchDoc: HV_VSYS, PP5V, VIN_3V3, RP_5V, PPHV

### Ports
HV_VSYS, PP5V, PPHV, RP_5V, VIN_3V3

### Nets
HV_VSYS: D1.1(K) ; port HV_VSYS, sheet U_PP5V_SUPPLY/HV_VSYS
PP5V: port PP5V, sheet U_PP5V_SUPPLY/PP5V
PPHV: port PPHV, sheet U_PP5V_SUPPLY/PPHV
RP_5V: port RP_5V, sheet U_PP5V_SUPPLY/RP_5V
TC_VSYS: D1.2(A) ; sheet U_IPP007_TC_POWER/TC_VSYS
VIN_3V3: port VIN_3V3, sheet U_PP5V_SUPPLY/VIN_3V3

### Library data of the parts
D1 = CMP-0067542-2: Diode, Schottky, 60 V, 5 A, SMA; Manufacturer: Micro Commercial Components; Value2: 0.75V; Vr_V: 60V; SizeZ_mm: 2.87; SizeAreaWB_mm2: 37.3428; Value: 60V; SizeX_mm: 5.59; AEC Qualified: N; Vf_V: 750mV; AEC Category: Q101; SizeArea_mm2: 16.3228; SizeY_mm: 2.92; Value1: 5A; TJmax_C: 150°C

## Sheet PP5V_SUPPLY.SchDoc
size 431 x 279 mm; Date: Not shown in title block; ApprovedBy: Not shown in title block; CheckedBy: Not shown in title block; Author: Not shown in title block; CompanyName: Not shown in title block; Engineer: Not shown in title block; Organization: Not shown in title block; Address1: Not shown in title block; Address2: Not shown in title block; Address3: Not shown in title block; Address4: Not shown in title block; DocumentNumber: 8; Revision: Use project parameter SCH_Rev; SheetNumber: 8; SheetTotal: 14; PageSetup: Record=PageOptions¦CenterHorizontal=True¦CenterVertical=True¦PrintScale=0.97¦XCorrection=1.00¦YCorrection=1.00¦PrintKind=0¦BorderSize=5000000¦LeftOffset=0¦BottomOffset=0¦Orientation=2¦PaperLength=1000¦PaperWidth=1000¦Scale=100¦PaperSource=15¦PrintQuality=600¦MediaType=1¦DitherType=10¦PaperKind=Letter¦PrintScaleMode=1
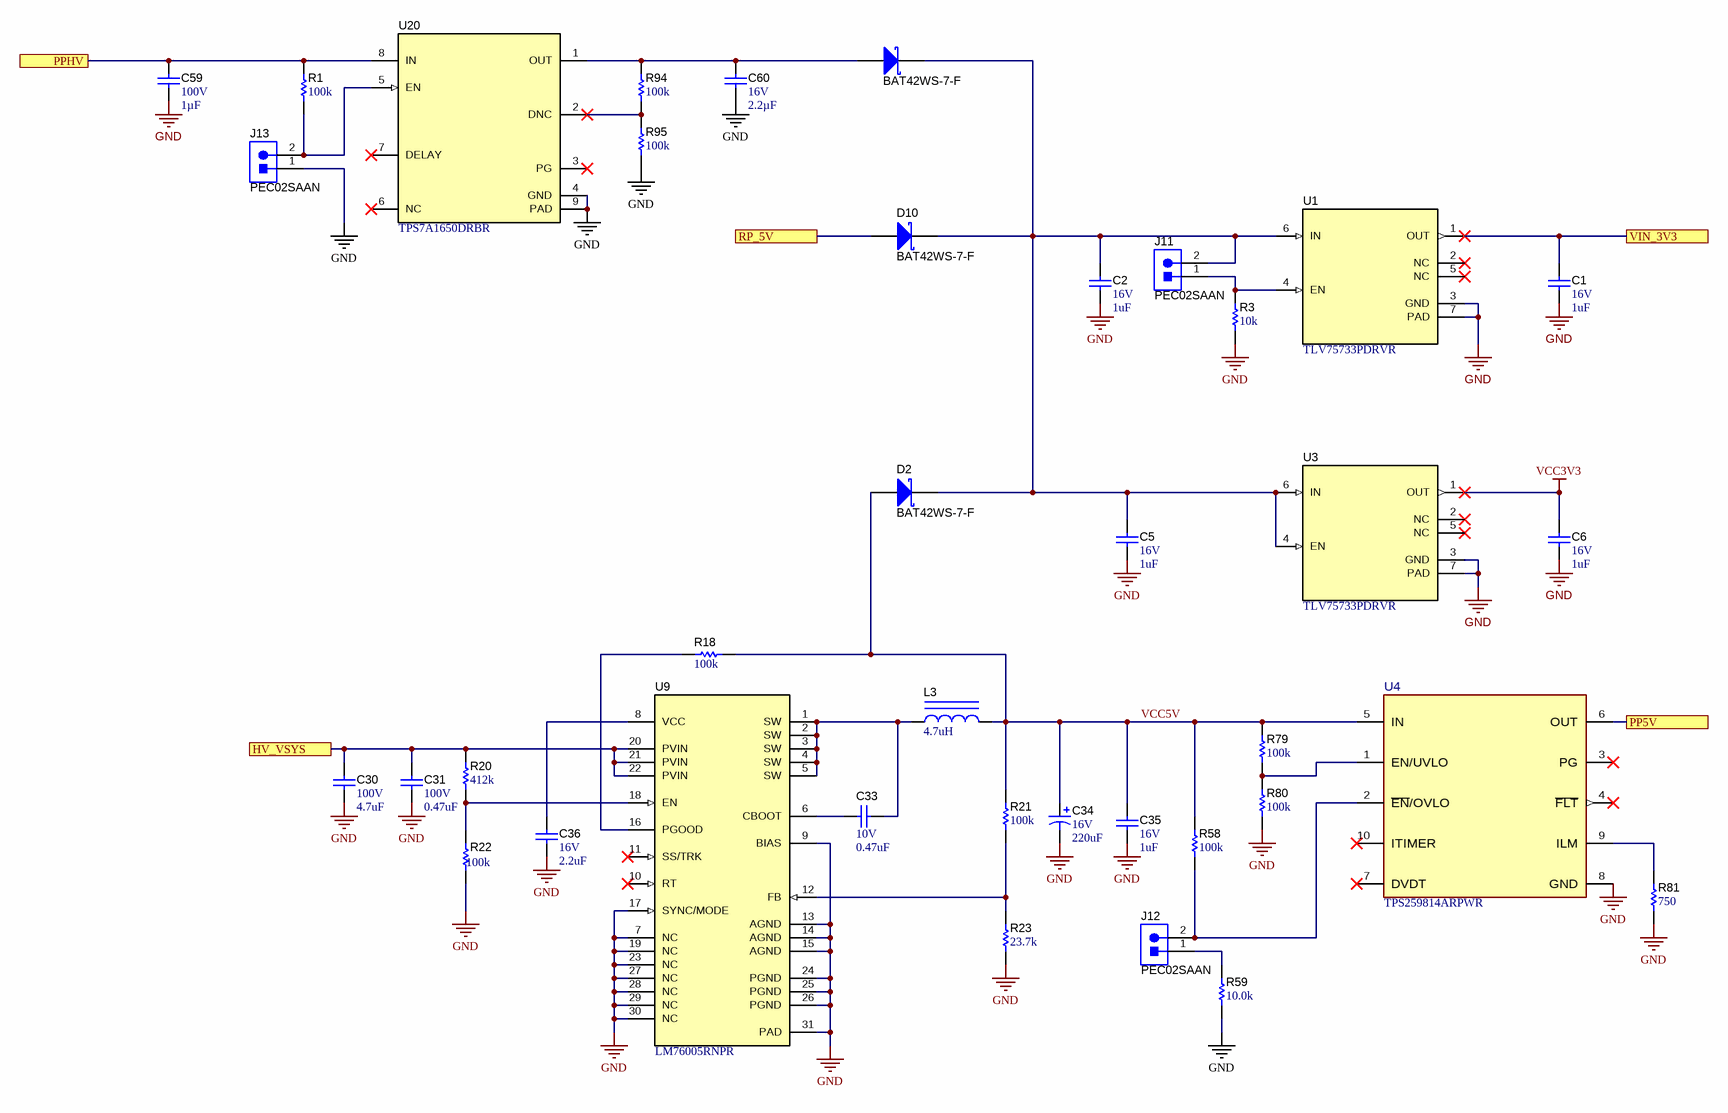
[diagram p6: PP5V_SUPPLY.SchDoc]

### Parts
C1  VDC_V: 16V  ValueDisplayed: 1uF  [0402L]  (hidden comment: C1005X6S1C105K050BC)
C2  VDC_V: 16V  ValueDisplayed: 1uF  [0402L]  (hidden comment: C1005X6S1C105K050BC)
C5  VDC_V: 16V  ValueDisplayed: 1uF  [0402L]  (hidden comment: C1005X6S1C105K050BC)
C6  VDC_V: 16V  ValueDisplayed: 1uF  [0402L]  (hidden comment: C1005X6S1C105K050BC)
C30  VDC_V: 100V  ValueDisplayed: 4.7uF  [1210L]  (hidden comment: C3225X7S2A475K200AE)
C31  VDC_V: 100V  ValueDisplayed: 0.47uF  [0805L]  (hidden comment: C2012X7S2A474K125AB)
C33  VDC_V: 10V  ValueDisplayed: 0.47uF  [0402L]  (hidden comment: GRM155R61A474KE15D)
C34  VDC_V: 16V  ValueDisplayed: 220uF  [7343-43]  (hidden comment: TPSE227M016R0100)
C35  VDC_V: 16V  ValueDisplayed: 1uF  [0402L]  (hidden comment: C1005X6S1C105K050BC)
C36  VDC_V: 16V  ValueDisplayed: 2.2uF  [0402_065L]  (hidden comment: C1005X6S1C225K050BC)
C59  VDC_V: 100V  ValueDisplayed: 1µF  [0805L]  (hidden comment: C2012X7S2A105K125AE)
C60  VDC_V: 16V  Cap_F: 2.2µF  [0603L]  (hidden comment: GRM188Z71C225KE43)
D2  BAT42WS-7-F  [SOD-323]
D5  BAT42WS-7-F  [SOD-323]
D10  BAT42WS-7-F  [SOD-323]
J11  PEC02SAAN  [CONN_PEC02SAAN]
J12  PEC02SAAN  [CONN_PEC02SAAN]
J13  PEC02SAAN  [CONN_PEC02SAAN]
L3  ValueDisplayed: 4.7uH  [XAL6060]  (hidden comment: XAL6060-472MEB)
R1  ValueDisplayed: 100k  [0402L]  (hidden comment: CRCW0402100KFKED)
R3  ValueDisplayed: 10k  [0402L]  (hidden comment: CRCW040210K0JNED)
R18  ValueDisplayed: 100k  [0402L]  (hidden comment: CRCW0402100KFKED)
R20  ValueDisplayed: 412k  [0402]  (hidden comment: CRCW0402412KFKED)
R21  ValueDisplayed: 100k  [0402L]  (hidden comment: CRCW0402100KFKED)
R22  ValueDisplayed: 100k  [0402L]  (hidden comment: CRCW0402100KFKED)
R23  ValueDisplayed: 23.7k  [0402L]  (hidden comment: ERJ-2RKF2372X)
R58  ValueDisplayed: 100k  [0402L]  (hidden comment: CRCW0402100KFKED)
R59  ValueDisplayed: 10.0k  [0201L]  (hidden comment: CRCW020110K0FKED)
R79  ValueDisplayed: 100k  [0402L]  (hidden comment: CRCW0402100KFKED)
R80  ValueDisplayed: 100k  [0402L]  (hidden comment: CRCW0402100KFKED)
R81  ValueDisplayed: 750  [0201L]  (hidden comment: RC0201FR-07750RL)
R94  ValueDisplayed: 100k  [0402L]  (hidden comment: CRCW0402100KFKED)
R95  ValueDisplayed: 100k  [0402L]  (hidden comment: CRCW0402100KFKED)
U1  TLV75733PDRVR  [DRV0006A]
U3  TLV75733PDRVR  [DRV0006A]
U4  TPS259814ARPWR  [RPW0010A-MFG]
U9  LM76005RNPR  [RNP0030A]
U20  TPS7A1650DRBR  [DRB0008B]

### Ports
HV_VSYS, PP5V, PPHV, RP_5V, VIN_3V3

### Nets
GND: C1.2 C2.2 C5.2 C6.2 C30.2 C31.2 C34.2(-) C35.2 C36.2 C59.2 C60.2 J13.1 R3.1 R22.2 R23.1 R59.2 R80.1 R81.1 R95.1 U1.3(GND) U1.7(PAD) U3.3(GND) U3.7(PAD) U4.8(GND) U9.7(NC) U9.9(BIAS) U9.13(AGND) U9.14(AGND) U9.15(AGND) U9.17(SYNC/MODE) U9.19(NC) U9.23(NC) U9.24(PGND) U9.25(PGND) U9.26(PGND) U9.27(NC) U9.28(NC) U9.29(NC) U9.30(NC) U9.31(PAD) U20.4(GND) U20.9(PAD)
VCC3V3: C6.1 U3.1(OUT)
HV_VSYS: C30.1 C31.1 R20.2 U9.20(PVIN) U9.21(PVIN) U9.22(PVIN) ; port HV_VSYS
PP5V: U4.6(OUT) ; port PP5V
PPHV: C59.1 R1.2 U20.8(IN) ; port PPHV
RP_5V: D10.2(A) ; port RP_5V
VCC5V: C34.1(+) C35.1 D2.2(A) L3.2 R18.2 R21.2 R58.2 R79.2 U4.5(IN)
VIN_3V3: C1.1 U1.1(OUT) ; port VIN_3V3
NetC2_1: C2.1 C5.1 D2.1(K) D5.1(K) D10.1(K) J11.2 U1.6(IN) U3.4(EN) U3.6(IN)
NetC33_1: C33.1 L3.1 U9.1(SW) U9.2(SW) U9.3(SW) U9.4(SW) U9.5(SW)
NetC33_2: C33.2 U9.6(CBOOT)
NetC36_1: C36.1 U9.8(VCC)
NetC60_1: C60.1 D5.2(A) R94.2 U20.1(OUT)
NetJ11_1: J11.1 R3.2 U1.4(EN)
NetJ12_1: J12.1 R59.1
NetJ12_2: J12.2 R58.1 U4.2(~{EN}/OVLO)
NetJ13_2: J13.2 R1.1 U20.5(EN)
NetR18_1: R18.1 U9.16(PGOOD)
NetR20_1: R20.1 R22.1 U9.18(EN)
NetR21_1: R21.1 R23.2 U9.12(FB)
NetR79_1: R79.1 R80.2 U4.1(EN/UVLO)
NetR81_2: R81.2 U4.9(ILM)
NetR94_1: R94.1 R95.2 U20.2(DNC)

Not connected (* = marked no-connect by the designer): U1 2(NC)* 5(NC)*; U3 2(NC)* 5(NC)*; U4 3(PG)* 4(~{FLT})* 7(DVDT)* 10(ITIMER)*; U9 10(RT)* 11(SS/TRK)*; U20 3(PG)* 6(NC)* 7(DELAY)*

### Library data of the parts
C1 C2 C5 C6 C35 = CMP-0006286-2: CAP, CERM, 1 uF, 16 V, +/- 10%, X6S, 0402; Manufacturer: TDK; TaMin_C: -55°C; ESR_ohm: 11.416m; Polarized: N; SizeAreaWB_mm2: 3; Value1: 0.011416 ohm; U/M: EA; Value: 1uF; TaMax_C: 105°C; SizeZ_mm: 0.6; SizeX_mm: 1; SizeY_mm: 0.5; Cap_Case: 0402; Cap_F: 1µF; IRMS_A: 1.483A; AEC Category: Q200
C30 = CMP-0009135-2: CAP, CERM, 4.7 uF, 100 V, +/- 10%, X7S, 1210; Manufacturer: TDK; TaMin_C: -55°C; Polarized: N; SizeAreaWB_mm2: 14.7; Value1: Unknown; U/M: EA; Value: 4.7uF; TaMax_C: 125°C; SizeZ_mm: 1.35; SizeX_mm: 3.2; SizeY_mm: 2.5; Cap_Case: 1210; SizeArea_mm2: 8; Cap_F: 4.7µF; AEC Category: Q200
C31 = CMP-0007895-2: CAP, CERM, 0.47 uF, 100 V, +/- 10%, X7S, 0805; Manufacturer: TDK; TaMin_C: -55°C; ESR_ohm: 17.152m; Polarized: N; SizeAreaWB_mm2: 6.75; Value1: 0.017152 ohm; U/M: EA; Value: 0.47uF; TaMax_C: 125°C; SizeZ_mm: 1.45; SizeX_mm: 2; SizeY_mm: 1.25; Cap_Case: 0805; SizeArea_mm2: 2.5; Cap_F: 470nF; IRMS_A: 1.5807A; AEC Category: Q200
C33 = CMP-0006580-2: CAP, CERM, 0.47 uF, 10 V, +/- 10%, X5R, 0402; Manufacturer: MuRata; TaMin_C: -55°C; Polarized: N; SizeAreaWB_mm2: 3; Value1: Unknown; U/M: EA; Value: 0.47uF; TaMax_C: 85°C; SizeZ_mm: 0.6; SizeX_mm: 1; SizeY_mm: 0.5; Cap_Case: 0402; Cap_F: 470nF; AEC Category: Q200
C34 = CMP-0011955-2: CAP, TA, 220 uF, 16 V, +/- 20%, 0.1 ohm, SMD; Manufacturer: AVX; TaMin_C: -55°C; ESR_ohm: 0.1; Polarized: Y; SizeAreaWB_mm2: 58.59; Value1: 0.1 ohm; U/M: EA; Value: 220uF; TaMax_C: 125°C; SizeZ_mm: 4.3; SizeX_mm: 7.3; Cap_Case: E; SizeArea_mm2: 31.39; CompType: Capacitor; Cap_F: 220µF; IRMS_A: 1.156A; AEC Category: Q200
C36 = CMP-0006288-2: CAP, CERM, 2.2 uF, 16 V, +/- 10%, X6S, 0402; Manufacturer: TDK; TaMin_C: -55°C; ESR_ohm: 5.925m; Polarized: N; SizeAreaWB_mm2: 3; Value1: 0.005925 ohm; U/M: EA; Value: 2.2uF; TaMax_C: 105°C; SizeZ_mm: 0.65; SizeX_mm: 1; SizeY_mm: 0.5; Cap_Case: 0402_065; Cap_F: 2.2µF; IRMS_A: 2.0559A; AEC Category: Q200
C59 = CMP-0750059-1: CAP, CERM, 1 µF, 100 V,+/- 10%, X7S, 0805; Manufacturer: TDK; TaMax_C: 125°C; SizeAreaWB_mm2: 6.75; SizeY_mm: 1.25; Green_REACh: Incomplete; TaMin_C: -55°C; Cap_Case: 0805; SizeZ_mm: 1.45; U/M: EA; SizeX_mm: 2; Polarized: N; Green_Lifecycle: Active; SizeArea_mm2: 2.5; Value: 1uF; AEC Category: Q200
C60 = CMP-0007499-4: CAP, CERM, 2.2 uF, 16 V, +/- 10%, X7R, 0603; Manufacturer: MuRata; TaMin_C: -55°C; Polarized: N; SizeAreaWB_mm2: 4.68; Value1: Unknown; U/M: EA; Value: 2.2uF; TaMax_C: 125°C; SizeZ_mm: 1; SizeX_mm: 1.6; SizeY_mm: 0.8; Cap_Case: 0603; SizeArea_mm2: 1.28; AEC Category: Q200
D2 D5 D10 = CMP-0028447-2: Diode, Schottky, 30 V, 0.2 A, SOD-323; Manufacturer: Diodes Inc.; SizeZ_mm: 1; AEC Category: Q101; Green_REACh: Incomplete; Green_Lifecycle: Not Set; Vr_V: 30V; Vf_V: 1V; Io_A: 200mA; SizeY_mm: 1.35; Value1: 0.2A; Value: 30V; SizeArea_mm2: 3.645; SizeX_mm: 2.7; SizeAreaWB_mm2: 8.695
J11-J13 = CMP-0002337-1: as J14 on sheet TPS26750
L3 = CMP-0061020-2: Inductor, Shielded, Composite, 4.7 µH, 10.5 A, 0.0144 ohm, AEC-Q200 Grade 1, SMD; Manufacturer: Coilcraft; SizeZ_mm: 6.1; Ind_H: 4.7µH; AEC Qualified: Y; Imax_A: 10.5A; Value: 4.7uH; SizeY_mm: 6.56; AEC Category: Q200; SizeAreaWB_mm2: 71.5616; Green_REACh: Incomplete; DCR_ohm: 14.4m; Isat: 10.5A @ 30% inductance drop; Green_Lifecycle: Not Set; SizeX_mm: 6.36; SizeArea_mm2: 41.7216; AEC Grade: 1; Irms: 12.3A @ 40C rise
R1 R18 R21 R22 R58 R79 R80 R94 R95 = CMP-0025950-3: RES, 100 k, 1%, 0.063 W, AEC-Q200 Grade 0, 0402; Manufacturer: Vishay-Dale; Power_W: 63mW; TempCo: 100 ppm/C; Value: 100k; EIA_Code: E96; SizeX_mm: 1; SizeY_mm: 0.5; SizeZ_mm: 0.6; Value2: 0.063W; AEC Qualified: Y; VDC_V: 50V; AEC Category: Q200; AEC Grade: 0
R3 = CMP-0026825-5: RES, 10 k, 5%, 0.063 W, AEC-Q200 Grade 0, 0402; Manufacturer: Vishay-Dale; Power_W: 63mW; TempCo: 200 ppm/C; Value_Code: 10k0; Value: 10k; EIA_Code: E24; SizeX_mm: 1; SizeY_mm: 0.5; SizeZ_mm: 0.6; Value2: 0.063W; AEC Qualified: Y; VDC_V: 50V; AEC Category: Q200; AEC Grade: 0
R20 = CMP-0026369-2: RES, 412 k, 1%, 0.063 W, AEC-Q200 Grade 0, 0402; Manufacturer: Vishay-Dale; Power_W: 63mW; TempCo: 100 ppm/C; Value: 412k; EIA_Code: E96; SizeX_mm: 1; SizeY_mm: 0.5; SizeZ_mm: 0.6; Value2: 0.063W; AEC Qualified: Y; VDC_V: 50V; AEC Category: Q200; AEC Grade: 0
R23 = CMP-0026683-1: RES, 23.7 k, 1%, 0.1 W, AEC-Q200 Grade 0, 0402; Manufacturer: Panasonic; Power_W: 100mW; TempCo: 100 ppm/C; Value_Code: 23k7; U/M: EA; Value: 23.7k; EIA_Code: E96; SizeX_mm: 1; SizeY_mm: 0.5; SizeZ_mm: 0.6; Value2: 0.1W; AEC Qualified: Y; VDC_V: 50V; AEC Grade: 0; AEC Category: Q200
R59 = CMP-0027262-3: as R38 on sheet TPS26750
R81 = CMP-0027865-1: RES, 750, 1%, 0.05 W, 0201; Manufacturer: Yageo America; Power_W: 50mW; TempCo: 200 ppm/C; Value_Code: 750R; U/M: EA; Value: 750; EIA_Code: E96; SizeX_mm: 0.6; SizeY_mm: 0.3; SizeZ_mm: 0.26; Value2: 0.05W; SizeArea_mm2: 0.18; AEC Qualified: N; VDC_V: 25V; AEC Category: Q200
U1 U3 = CMP-0074651-9: 1A Low-Quiescent-Current Low-Dropout (LDO) Regulator, DRV0006A (WSON-6); Manufacturer: Texas Instruments; SizeX_mm: 2; CompType: IC; SizeZ_mm: 0.8; SizeArea_mm2: 4; SizeAreaWB_mm2: 9; AEC Category: Q200; AEC Qualified: N; Rating: Catalog
U4 = CMP-0093419-2: 2.7- 16 V, 10 A, 7 mΩ eFuse with transient overcurrent blanking timer; Manufacturer: Texas Instruments; AEC Qualified: No; AEC Category: Q200; TJmax_C: +125°C; CompType: IC; Min Supply Voltage: 2.7V; Standoff Height: 0mm; Max Supply Voltage: 16V; SizeZ_mm: 1mm; Number Of Outputs: 1; Output Voltage: 0-16V; Nominal Supply Current: 430uA
U9 = CMP-0861019-1: 3.5V to 60V 5A Synchronous Step-Down Voltage Regulator, RNP0030A (WQFN-30); Alternate Manufacturer: Texas Instruments; AEC Category: Q200; SizeArea_mm2: 24; SizeX_mm: 4; SizeZ_mm: 0.8; AEC Qualified: N; SizeAreaWB_mm2: 48; SizeY_mm: 6; CompType: IC
U20 = CMP-0079946-1: 60V, 5uA Iq, 100mA Low-Dropout (LDO) Voltage Regulator With Enable and Power Good, DRB0008B (VSON-8); Alternate PartNumber: TPS7A1650DRBT; Alternate Manufacturer: Texas Instruments; SizeAreaWB_mm2: 16; SizeZ_mm: 1; SizeX_mm: 3; SizeArea_mm2: 9; CompType: IC; AEC Qualified: N; AEC Category: Q200

## Sheet IPP007_TC_POWER.SchDoc
size 431 x 279 mm; Date: Not shown in title block; ApprovedBy: Not shown in title block; CheckedBy: Not shown in title block; Author: Not shown in title block; CompanyName: Not shown in title block; Engineer: Not shown in title block; Organization: Not shown in title block; Address1: Not shown in title block; Address2: Not shown in title block; Address3: Not shown in title block; Address4: Not shown in title block; DocumentNumber: 9; Revision: Use project parameter SCH_Rev; SheetNumber: 9; SheetTotal: 14; PageSetup: Record=PageOptions¦CenterHorizontal=True¦CenterVertical=True¦PrintScale=1.00¦XCorrection=1.00¦YCorrection=1.00¦PrintKind=0¦BorderSize=5000000¦LeftOffset=0¦BottomOffset=0¦Orientation=2¦PaperLength=1000¦PaperWidth=1000¦Scale=100¦PaperSource=15¦PrintQuality=600¦MediaType=1¦DitherType=10¦PaperKind=Letter¦PrintScaleMode=1
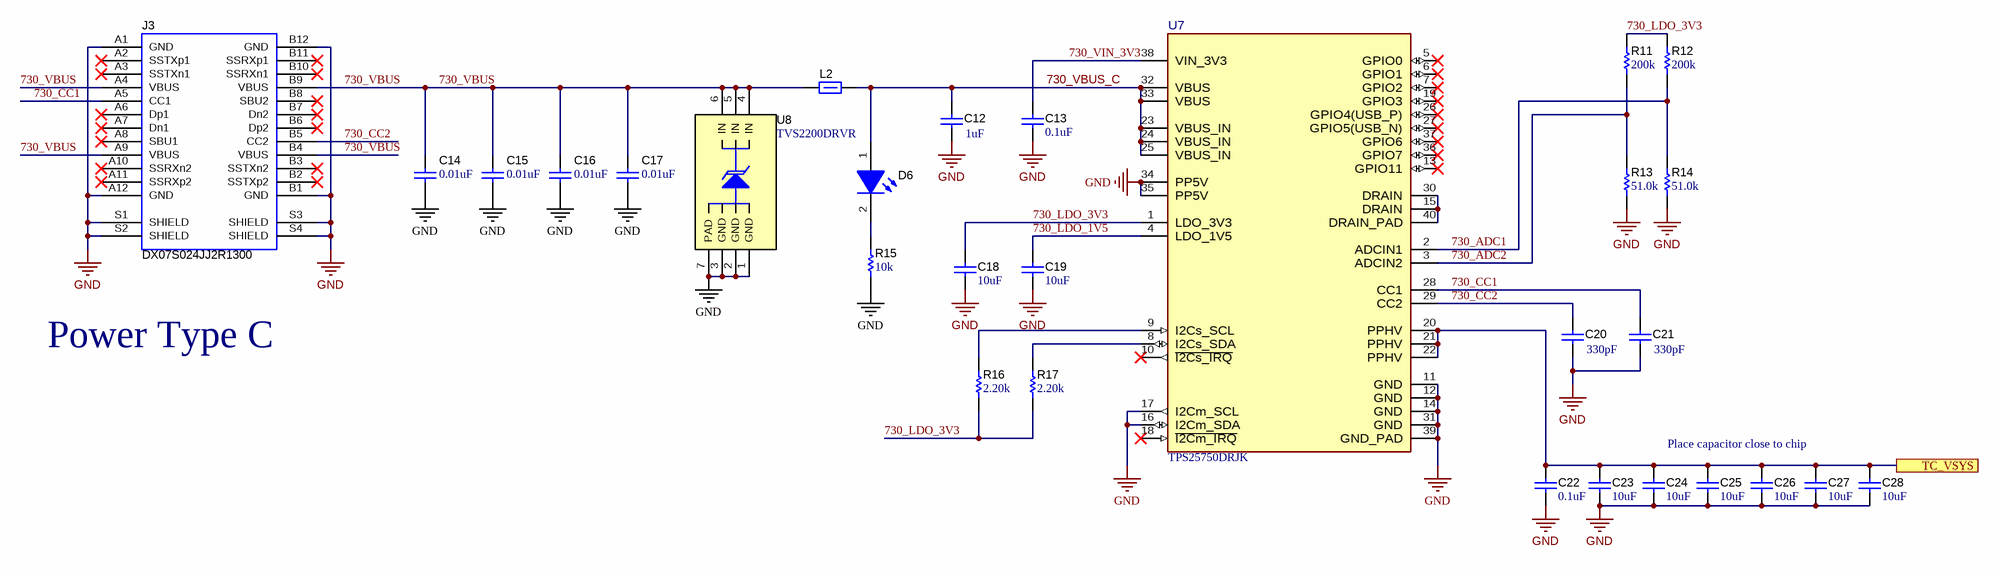
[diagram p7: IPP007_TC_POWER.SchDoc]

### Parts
C12  ValueDisplayed: 1uF  [0402L]  (hidden comment: GRM155R6YA105KE11D)
C13  ValueDisplayed: 0.1uF  [0402L]  (hidden comment: GMK105BJ104KV-F)
C14  ValueDisplayed: 0.01uF  [0402L]  (hidden comment: C0402C103J5RACTU)
C15  ValueDisplayed: 0.01uF  [0402L]  (hidden comment: C0402C103J5RACTU)
C16  ValueDisplayed: 0.01uF  [0402L]  (hidden comment: C0402C103J5RACTU)
C17  ValueDisplayed: 0.01uF  [0402L]  (hidden comment: C0402C103J5RACTU)
C18  ValueDisplayed: 10uF  [0402_070]  (hidden comment: CL05A106MP5NUNC)
C19  ValueDisplayed: 10uF  [0402_070]  (hidden comment: CL05A106MP5NUNC)
C20  ValueDisplayed: 330pF  [0201_033L]  (hidden comment: CGA1A2X7R1H331K030BA)
C21  ValueDisplayed: 330pF  [0201_033L]  (hidden comment: CGA1A2X7R1H331K030BA)
C22  ValueDisplayed: 0.1uF  [0402L]  (hidden comment: GMK105BJ104KV-F)
C23  ValueDisplayed: 10uF  [0603L]  (hidden comment: GRM188R6YA106MA73D)
C24  ValueDisplayed: 10uF  [0603L]  (hidden comment: GRM188R6YA106MA73D)
C25  ValueDisplayed: 10uF  [0603L]  (hidden comment: GRM188R6YA106MA73D)
C26  ValueDisplayed: 10uF  [0603L]  (hidden comment: GRM188R6YA106MA73D)
C27  ValueDisplayed: 10uF  [0603L]  (hidden comment: GRM188R6YA106MA73D)
C28  ValueDisplayed: 10uF  [0603L]  (hidden comment: GRM188R6YA106MA73D)
D6  LW QH8G-Q2S2-3K5L-1  [LW QH8G_White]  (value not drawn)
J3  DX07S024JJ2R1300  [JAE_DX07S024JJ2R1300]
L2  742792021  [0805L]  (value not drawn)
R11  ValueDisplayed: 200k  [0201_033L]  (hidden comment: CRCW0201200KFKED)
R12  ValueDisplayed: 200k  [0201_033L]  (hidden comment: CRCW0201200KFKED)
R13  ValueDisplayed: 51.0k  [0201L]  (hidden comment: RC0201FR-0751KL)
R14  ValueDisplayed: 51.0k  [0201L]  (hidden comment: RC0201FR-0751KL)
R15  ValueDisplayed: 10k  [0402L]  (hidden comment: CRCW040210K0JNED)
R16  ValueDisplayed: 2.20k  [0201L]  (hidden comment: CRCW02012K20FKED)
R17  ValueDisplayed: 2.20k  [0201L]  (hidden comment: CRCW02012K20FKED)
U7  TPS25750DRJK  [RJK0038B-C01-MFG]
U8  TVS2200DRVR  [DRV0006A]

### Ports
TC_VSYS

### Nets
GND: C12.2 C13.2 C14.2 C15.2 C16.2 C17.2 C18.1 C19.1 C20.2 C21.2 C22.2 C23.2 C24.2 C25.2 C26.2 C27.2 C28.2 J3.A1(GND) J3.A12(GND) J3.B1(GND) J3.B12(GND) J3.S1(SHIELD) J3.S2(SHIELD) J3.S3(SHIELD) J3.S4(SHIELD) R13.1 R14.1 R15.1 U7.11(GND) U7.12(GND) U7.14(GND) U7.16(I2Cm_SDA) U7.17(I2Cm_SCL) U7.31(GND) U7.34(PP5V) U7.35(PP5V) U7.39(GND_PAD) U8.1(GND) U8.2(GND) U8.3(GND) U8.7(PAD)
730_ADC1: R12.1 R14.2 U7.2(ADCIN1)
730_ADC2: R11.1 R13.2 U7.3(ADCIN2)
730_CC1: C21.1 J3.A5(CC1) U7.28(CC1)
730_CC2: C20.1 J3.B5(CC2) U7.29(CC2)
730_LDO_1V5: C19.2 U7.4(LDO_1V5)
730_LDO_3V3: C18.2 R11.2 R12.2 R16.1 R17.1 U7.1(LDO_3V3)
730_VBUS: C14.1 C15.1 C16.1 C17.1 J3.A4(VBUS) J3.A9(VBUS) J3.B4(VBUS) J3.B9(VBUS) L2.1 U8.4(IN) U8.5(IN) U8.6(IN)
730_VBUS_C: C12.1 D6.1(A) L2.2 U7.23(VBUS_IN) U7.24(VBUS_IN) U7.25(VBUS_IN) U7.32(VBUS) U7.33(VBUS)
730_VIN_3V3: C13.1 U7.38(VIN_3V3)
TC_VSYS: C22.1 C23.1 C24.1 C25.1 C26.1 C27.1 C28.1 U7.20(PPHV) U7.21(PPHV) U7.22(PPHV) ; port TC_VSYS
NetD6_2: D6.2(K) R15.2
NetR16_2: R16.2 U7.9(I2Cs_SCL)
NetR17_2: R17.2 U7.8(I2Cs_SDA)
NetU7_15: U7.15(DRAIN) U7.30(DRAIN) U7.40(DRAIN_PAD)

Not connected (* = marked no-connect by the designer): J3 A2(SSTXp1)* A3(SSTXn1)* A6(Dp1)* A7(Dn1)* A8(SBU1)* A10(SSRXn2)* A11(SSRXp2)* B2(SSTXp2)* B3(SSTXn2)* B6(Dp2)* B7(Dn2)* B8(SBU2)* B10(SSRXn1)* B11(SSRXp1)*; U7 5(GPIO0)* 6(GPIO1)* 7(GPIO2)* 10(~{I2Cs_IRQ})* 13(GPIO11)* 18(~{I2Cm_IRQ})* 19(GPIO3)* 26(GPIO4(USB_P))* 27(GPIO5(USB_N))* 36(GPIO7)* 37(GPIO6)*

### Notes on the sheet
- Power Type C
- Place capacitor close to chip

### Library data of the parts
C12 = CMP-0006619-2: CAP, CERM, 1 uF, 35 V, +/- 10%, X5R, 0402; Manufacturer: MuRata; TaMin_C: -55°C; Polarized: N; SizeAreaWB_mm2: 3; Value1: Unknown; U/M: EA; Value: 1uF; TaMax_C: 85°C; SizeZ_mm: 0.6; SizeX_mm: 1; SizeY_mm: 0.5; Cap_Case: 0402; Value2: 35V; Cap_F: 1µF; AEC Category: Q200
C13 C22 = CMP-0006370-2: CAP, CERM, 0.1 uF, 35 V, +/- 10%, X5R, 0402; Manufacturer: Taiyo Yuden; TaMin_C: -55°C; Polarized: N; SizeAreaWB_mm2: 3; Value1: Unknown; U/M: EA; Value: 0.1uF; TaMax_C: 85°C; SizeZ_mm: 0.6; SizeX_mm: 1; SizeY_mm: 0.5; Cap_Case: 0402; Value2: 35V; Cap_F: 100nF; AEC Category: Q200
C14-C17 = CMP-0006236-2: CAP, CERM, 0.01 uF, 50 V, +/- 5%, X7R, 0402; Manufacturer: Kemet; TaMin_C: -55°C; Polarized: N; SizeAreaWB_mm2: 3; Value1: Unknown; U/M: EA; Value: 0.01uF; TaMax_C: 125°C; SizeZ_mm: 0.6; SizeX_mm: 1; SizeY_mm: 0.5; Cap_Case: 0402; Value2: 50V; Cap_F: 10nF; AEC Category: Q200
C18 C19 = CMP-0006339-4: as C42 on sheet TPS26750
C20 C21 = CMP-0009653-3: CAP, CERM, 330 pF, 50 V, +/- 10%, X7R, AEC-Q200 Grade 1, 0201; Manufacturer: TDK; TaMin_C: -55°C; ESR_ohm: 8.053; Polarized: N; SizeAreaWB_mm2: 2.08; Value1: 8.05302 ohm; U/M: EA; Value: 330pF; TaMax_C: 125°C; SizeZ_mm: 0.33; SizeX_mm: 0.6; SizeY_mm: 0.3; Cap_Case: 0201_033; Value2: 50V; SizeArea_mm2: 0.18; AEC Qualified: Y; IRMS_A: 210.618mA; AEC Grade: 1; AEC Category: Q200
C23-C28 = CMP-0007355-6: CAP, CERM, 10 uF, 35 V, +/- 20%, X5R, 0603; Manufacturer: Murata; TaMax_C: 85°C; Value1: Unknown; Value2: 35V; TaMin_C: -55°C; Value: 10uF; SizeZ_mm: 1; SizeArea_mm2: 1.28; AEC Category: Q200; Cap_F: 10µF; SizeY_mm: 0.8; AEC Qualified: N; SizeX_mm: 1.6; SizeAreaWB_mm2: 4.68; U/M: EA; Cap_Case: 0603
D6 = CMP-0002919-2: LED, White, SMD; Manufacturer: OSRAM; Io_A: 5mA; Vr_V: 5V; Tjmax_C: 95°C; Value1: W; Angle: 120; Ir_A: 10nA; Vf_V: 2.8V
J3 = CMP-0085712-2: as J4 on sheet TPS26750
L2 = CMP-0003072-1: as L4 on sheet TPS26750
R11 R12 = CMP-0078704-2: RES, 200 k, 1%, 0.05 W, 0201; Manufacturer: Vishay-Dale; SizeArea_mm2: 0.18; AEC Qualified: N; AEC Category: Q200; Value: 200k; SizeZ_mm: 0.33; EIA_Code: E96; TempCo: 100 ppm/C; Power_W: 50mW; VDC_V: 30V; SizeY_mm: 0.3; Value2: 0.05W; SizeX_mm: 0.6
R13 R14 = CMP-0027757-1: RES, 51.0 k, 1%, 0.05 W, 0201; Manufacturer: Yageo America; Power_W: 50mW; TempCo: 200 ppm/C; Value_Code: 51k0; U/M: EA; Value: 51.0k; Res_ohm: 51k; SizeX_mm: 0.6; SizeY_mm: 0.3; SizeZ_mm: 0.26; Value2: 0.05W; SizeArea_mm2: 0.18; AEC Qualified: N; VDC_V: 25V; AEC Category: Q200
R15 = CMP-0026825-5: as R3 on sheet PP5V_SUPPLY
R16 R17 = CMP-0027272-3: as R36 on sheet TPS26750
U7 = CMP-0090338-5: USB Type-C and USB PD Controller with Integrated Power Switches Optimized for Power Applications; Manufacturer: Texas Instruments; CompType: IC; Usb Standard: USB 3.0; AEC Category: Q200; SizeZ_mm: 0.8mm; Standoff Height: 0mm; AEC Qualified: No; Max Supply Voltage: 22V; TaMax_C: +105°C; Min Supply Voltage: 3V; TaMin_C: -40°C; TJmax_C: +175°C; Number Of Ports: 1
U8 = CMP-0077834-1: 22-V Precision Surge Protection Clamp, DRV0006A (WSON-6); Alternate Manufacturer: Texas Instruments; SizeAreaWB_mm2: 9.0; SizeZ_mm: 0.8; SizeX_mm: 2.0; SizeArea_mm2: 4.0; CompType: IC; AEC Qualified: N; AEC Category: Q200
